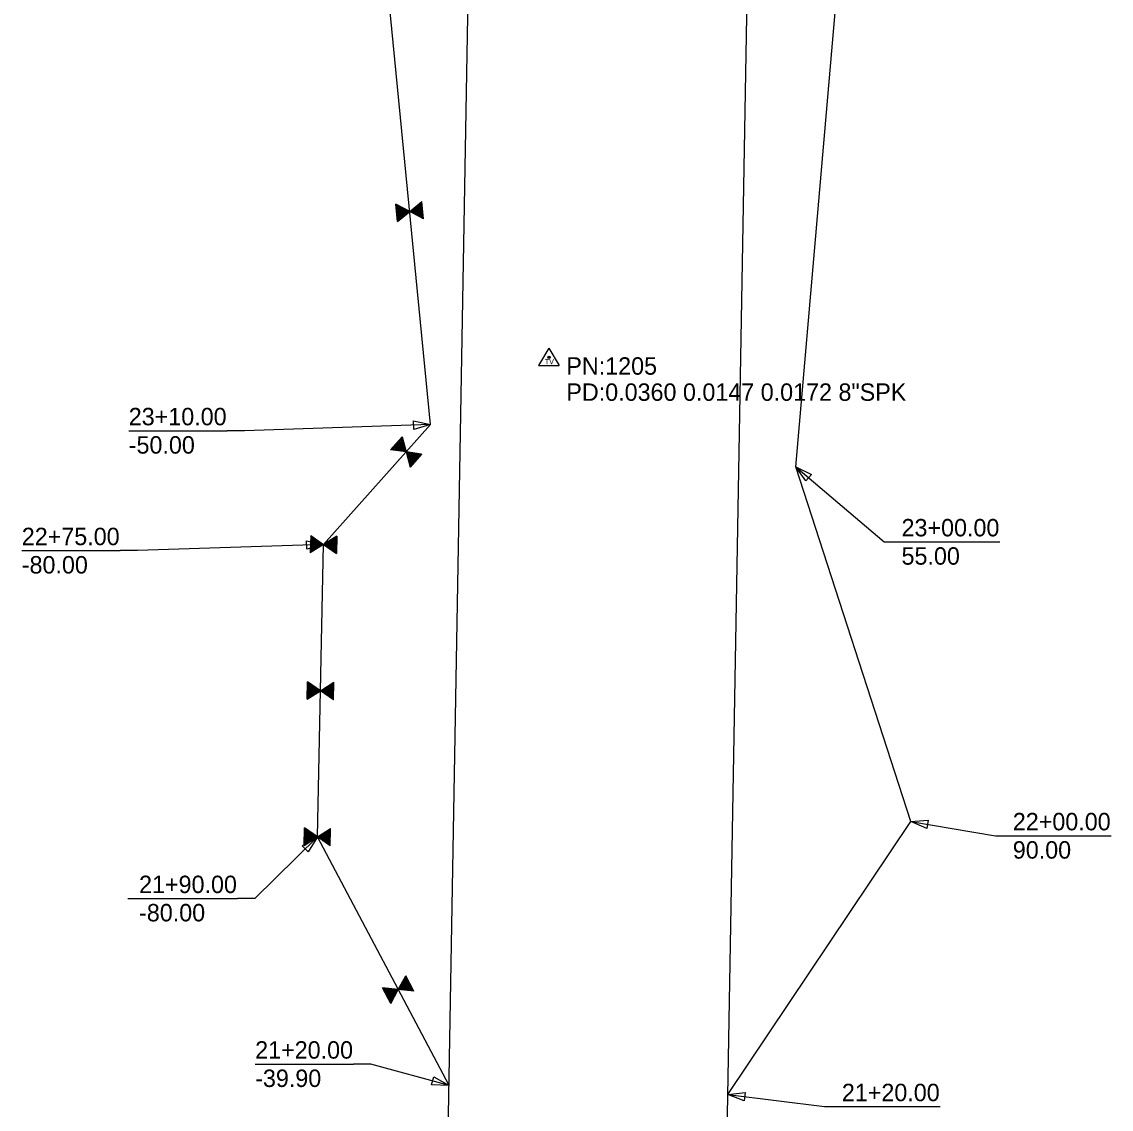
# Model space of a CAD drawing. Extents: x 1443798 to 1476449, y 2041559 to 2057889.
# Drawn here: x 1476064 to 1476376.6, y 2054853 to 2055165 of the extents above; entities that cross this region are included whole.
import ezdxf

# ---------------------------------------------------------------- set-up
doc = ezdxf.new("R2010")
doc.units = 0
for name, color, linetype in [('Plan Notes', 7, 'Continuous'), ('R_Proposed Fence', 7, 'Continuous'), ('R_ROW', 7, 'Continuous'), ('S_EXIST_ROW', 7, 'Continuous'), ('S_SECONDARY_CTL', 7, 'Continuous'), ('S_SECONDARY_CTL_ANNOT', 7, 'Continuous')]:
    doc.layers.add(name, color=color, linetype=linetype)

msp = doc.modelspace()

# ---------------------------------------------------------------- linework, layer by layer
at = {"layer": 'Plan Notes'}
for p, q in [((1476094.73, 2055047.66), (1476122.96, 2055047.66)), ((1476316.45, 2055015.79), (1476344.68, 2055015.79)), ((1476064.04, 2055013.26), (1476092.27, 2055013.26)), ((1476348.37, 2054931.44), (1476376.6, 2054931.44)), ((1476094.46, 2054913.43), (1476125.92, 2054913.43)), ((1476131, 2054865.91), (1476159.23, 2054865.91)), ((1476299.32, 2054853.71), (1476327.56, 2054853.71))]:
    msp.add_line(p, q, dxfattribs=at)
for points in [[(1476181.31, 2055049.43), (1476127.96, 2055047.66), (1476122.96, 2055047.66)], [(1476286.09, 2055037.35), (1476311.45, 2055015.79), (1476316.45, 2055015.79)], [(1476150.62, 2055015.03), (1476097.27, 2055013.26), (1476092.27, 2055013.26)], [(1476319.08, 2054935.51), (1476343.37, 2054931.44), (1476348.37, 2054931.44)], [(1476148.84, 2054931.09), (1476130.92, 2054913.43), (1476125.92, 2054913.43)], [(1476186.62, 2054859.81), (1476164.23, 2054865.91), (1476159.23, 2054865.91)], [(1476266.59, 2054857.19), (1476294.32, 2054853.71), (1476299.32, 2054853.71)]]:
    msp.add_lwpolyline(points, dxfattribs=at)
for points in [[(1476181.31, 2055049.43), (1476176.5, 2055048.06), (1476176.42, 2055050.48)], [(1476286.09, 2055037.35), (1476290.57, 2055035.14), (1476289, 2055033.29)], [(1476150.62, 2055015.03), (1476145.82, 2055013.66), (1476145.74, 2055016.08)], [(1476319.08, 2054935.51), (1476324.06, 2054935.9), (1476323.66, 2054933.51)], [(1476148.84, 2054931.09), (1476146.24, 2054926.82), (1476144.53, 2054928.55)], [(1476186.62, 2054859.81), (1476181.62, 2054859.92), (1476182.26, 2054862.26)], [(1476266.59, 2054857.19), (1476271.55, 2054857.79), (1476271.25, 2054855.38)]]:
    msp.add_lwpolyline(points, close=True, dxfattribs=at)
at = {"layer": 'R_Proposed Fence'}
for p, q in [((1476175.34, 2055110.56), (1476171.37, 2055112.68)), ((1476175.25, 2055110.51), (1476171.38, 2055112.58)), ((1476175, 2055110.36), (1476171.41, 2055112.28)), ((1476174.84, 2055110.17), (1476171.44, 2055111.98)), ((1476174.61, 2055110.01), (1476171.46, 2055111.69)), ((1476175.34, 2055110.56), (1476178.83, 2055113.41)), ((1476175.44, 2055110.53), (1476178.84, 2055113.31)), ((1476175.71, 2055110.43), (1476178.87, 2055113.01)), ((1476175.92, 2055110.27), (1476178.9, 2055112.71)), ((1476176.17, 2055110.16), (1476178.93, 2055112.42)), ((1476176.39, 2055110.02), (1476178.96, 2055112.12)), ((1476176.67, 2055109.92), (1476178.99, 2055111.82)), ((1476174.42, 2055109.83), (1476171.49, 2055111.39)), ((1476174.16, 2055109.68), (1476171.52, 2055111.09)), ((1476174, 2055109.48), (1476171.55, 2055110.79)), ((1476173.75, 2055109.33), (1476171.58, 2055110.49)), ((1476173.55, 2055109.15), (1476171.61, 2055110.19)), ((1476173.16, 2055108.8), (1476171.67, 2055109.59)), ((1476172.97, 2055108.62), (1476171.7, 2055109.29)), ((1476172.74, 2055108.45), (1476171.73, 2055109)), ((1476172.51, 2055108.29), (1476171.76, 2055108.7)), ((1476173.29, 2055109.01), (1476171.79, 2055109.81)), ((1476171.85, 2055107.71), (1476175.34, 2055110.56)), ((1476179.32, 2055108.44), (1476175.34, 2055110.56)), ((1476176.87, 2055109.76), (1476179.02, 2055111.52)), ((1476177.15, 2055109.67), (1476179.05, 2055111.22)), ((1476177.37, 2055109.53), (1476179.08, 2055110.92)), ((1476177.65, 2055109.43), (1476178.98, 2055110.52)), ((1476177.83, 2055109.25), (1476179.13, 2055110.32)), ((1476178.05, 2055109.11), (1476179.16, 2055110.02)), ((1476178.3, 2055109), (1476179.19, 2055109.72)), ((1476178.56, 2055108.88), (1476179.22, 2055109.43)), ((1476178.78, 2055108.74), (1476179.25, 2055109.13)), ((1476179.03, 2055108.63), (1476179.28, 2055108.83)), ((1476179.26, 2055108.49), (1476179.31, 2055108.53)), ((1476172.32, 2055108.11), (1476171.79, 2055108.4)), ((1476172.09, 2055107.95), (1476171.82, 2055108.1)), ((1476171.9, 2055107.77), (1476171.84, 2055107.8)), ((1476173.16, 2055045.93), (1476174.3, 2055041.57)), ((1476174.03, 2055042.45), (1476170.5, 2055042.94)), ((1476173.98, 2055042.7), (1476170.7, 2055043.17)), ((1476173.87, 2055042.97), (1476170.9, 2055043.39)), ((1476173.85, 2055043.23), (1476171.1, 2055043.62)), ((1476173.73, 2055043.5), (1476171.3, 2055043.84)), ((1476173.68, 2055043.76), (1476171.5, 2055044.06)), ((1476173.56, 2055044.03), (1476171.87, 2055044.27)), ((1476173.57, 2055044.28), (1476171.9, 2055044.51)), ((1476173.52, 2055044.54), (1476172.1, 2055044.74)), ((1476173.44, 2055044.8), (1476172.3, 2055044.96)), ((1476173.35, 2055045.07), (1476172.5, 2055045.19)), ((1476173.3, 2055045.33), (1476172.7, 2055045.41)), ((1476173.21, 2055045.59), (1476172.9, 2055045.63)), ((1476173.17, 2055045.85), (1476173.1, 2055045.86)), ((1476174.3, 2055041.57), (1476169.83, 2055042.2)), ((1476174.25, 2055041.66), (1476169.9, 2055042.27)), ((1476174.14, 2055041.93), (1476170.1, 2055042.5)), ((1476174.12, 2055042.18), (1476170.3, 2055042.72)), ((1476174.3, 2055041.57), (1476175.43, 2055037.2)), ((1476178.76, 2055040.94), (1476174.3, 2055041.57)), ((1476174.39, 2055041.53), (1476175.5, 2055037.28)), ((1476174.67, 2055041.45), (1476175.7, 2055037.5)), ((1476174.93, 2055041.46), (1476175.9, 2055037.73)), ((1476175.2, 2055041.4), (1476176.1, 2055037.95)), ((1476175.46, 2055041.38), (1476176.3, 2055038.18)), ((1476175.74, 2055041.3), (1476176.5, 2055038.4)), ((1476176, 2055041.31), (1476176.7, 2055038.62)), ((1476176.28, 2055041.22), (1476176.9, 2055038.85)), ((1476176.54, 2055041.2), (1476177.1, 2055039.07)), ((1476176.83, 2055041.11), (1476177.26, 2055039.46)), ((1476177.07, 2055041.16), (1476177.5, 2055039.52)), ((1476177.34, 2055041.14), (1476177.7, 2055039.74)), ((1476177.61, 2055041.08), (1476177.9, 2055039.97)), ((1476177.88, 2055041.02), (1476178.1, 2055040.19)), ((1476178.15, 2055041.01), (1476178.3, 2055040.42)), ((1476178.42, 2055040.95), (1476178.5, 2055040.64)), ((1476178.68, 2055040.93), (1476178.7, 2055040.87)), ((1476150.53, 2055015.07), (1476146.82, 2055012.71)), ((1476150.62, 2055015.03), (1476146.82, 2055012.61)), ((1476150.27, 2055015.2), (1476146.83, 2055013.01)), ((1476149.85, 2055015.52), (1476146.84, 2055013.61)), ((1476150.09, 2055015.38), (1476146.84, 2055013.31)), ((1476149.65, 2055015.69), (1476146.85, 2055013.91)), ((1476149.2, 2055016), (1476146.86, 2055014.51)), ((1476149.38, 2055015.82), (1476146.86, 2055014.21)), ((1476148.94, 2055016.13), (1476146.87, 2055014.81)), ((1476148.73, 2055016.29), (1476146.88, 2055015.11)), ((1476148.11, 2055016.78), (1476146.89, 2055016.01)), ((1476148.31, 2055016.62), (1476146.89, 2055015.71)), ((1476147.87, 2055016.93), (1476146.9, 2055016.31)), ((1476147.43, 2055017.24), (1476146.91, 2055016.91)), ((1476147.63, 2055017.07), (1476146.91, 2055016.61)), ((1476147.19, 2055017.38), (1476146.92, 2055017.21)), ((1476146.93, 2055017.61), (1476150.62, 2055015.03)), ((1476146.98, 2055017.55), (1476146.93, 2055017.52)), ((1476148.46, 2055016.42), (1476147.02, 2055015.5)), ((1476154.43, 2055017.45), (1476150.62, 2055015.03)), ((1476150.62, 2055015.03), (1476154.32, 2055012.45)), ((1476150.72, 2055015.07), (1476154.32, 2055012.55)), ((1476150.99, 2055015.18), (1476154.33, 2055012.85)), ((1476151.17, 2055015.36), (1476154.34, 2055013.15)), ((1476151.42, 2055015.49), (1476154.34, 2055013.45)), ((1476151.63, 2055015.65), (1476154.35, 2055013.75)), ((1476151.9, 2055015.76), (1476154.35, 2055014.05)), ((1476152.09, 2055015.94), (1476154.36, 2055014.35)), ((1476152.36, 2055016.06), (1476154.37, 2055014.65)), ((1476152.57, 2055016.21), (1476154.37, 2055014.95)), ((1476152.84, 2055016.33), (1476154.24, 2055015.35)), ((1476153, 2055016.52), (1476154.39, 2055015.55)), ((1476153.21, 2055016.68), (1476154.39, 2055015.85)), ((1476153.46, 2055016.81), (1476154.4, 2055016.15)), ((1476153.7, 2055016.94), (1476154.41, 2055016.45)), ((1476153.91, 2055017.1), (1476154.41, 2055016.76)), ((1476154.16, 2055017.24), (1476154.42, 2055017.05)), ((1476154.37, 2055017.39), (1476154.43, 2055017.36)), ((1476148.46, 2054972.32), (1476146, 2054974.04)), ((1476148.73, 2054972.44), (1476146.01, 2054974.34)), ((1476149.18, 2054972.73), (1476146.02, 2054974.94)), ((1476148.94, 2054972.6), (1476146.02, 2054974.64)), ((1476149.64, 2054973.02), (1476146.03, 2054975.54)), ((1476149.37, 2054972.91), (1476146.03, 2054975.24)), ((1476149.73, 2054973.06), (1476146.04, 2054975.64)), ((1476149.73, 2054973.06), (1476153.54, 2054975.48)), ((1476149.82, 2054973.02), (1476153.53, 2054975.38)), ((1476150.09, 2054972.89), (1476153.53, 2054975.08)), ((1476150.27, 2054972.71), (1476153.52, 2054974.78)), ((1476150.51, 2054972.57), (1476153.51, 2054974.48)), ((1476150.71, 2054972.4), (1476153.51, 2054974.18)), ((1476145.93, 2054970.64), (1476149.73, 2054973.06)), ((1476146.2, 2054970.85), (1476145.94, 2054971.03)), ((1476146.65, 2054971.14), (1476145.95, 2054971.63)), ((1476146.44, 2054970.99), (1476145.95, 2054971.33)), ((1476147.14, 2054971.41), (1476145.96, 2054972.24)), ((1476146.9, 2054971.28), (1476145.96, 2054971.93)), ((1476147.36, 2054971.57), (1476145.97, 2054972.54)), ((1476147.79, 2054971.88), (1476145.98, 2054973.14)), ((1476148, 2054972.03), (1476145.99, 2054973.44)), ((1476148.27, 2054972.15), (1476146, 2054973.74)), ((1476147.51, 2054971.76), (1476146.11, 2054972.74)), ((1476153.43, 2054970.48), (1476149.73, 2054973.06)), ((1476150.97, 2054972.27), (1476153.5, 2054973.88)), ((1476151.16, 2054972.09), (1476153.49, 2054973.58)), ((1476151.42, 2054971.96), (1476153.49, 2054973.28)), ((1476151.62, 2054971.79), (1476153.48, 2054972.98)), ((1476151.89, 2054971.67), (1476153.33, 2054972.59)), ((1476152.04, 2054971.47), (1476153.47, 2054972.38)), ((1476152.25, 2054971.3), (1476153.46, 2054972.08)), ((1476152.49, 2054971.16), (1476153.46, 2054971.78)), ((1476152.73, 2054971.02), (1476153.45, 2054971.48)), ((1476152.93, 2054970.85), (1476153.44, 2054971.17)), ((1476145.99, 2054970.7), (1476145.93, 2054970.73)), ((1476153.17, 2054970.71), (1476153.44, 2054970.87)), ((1476153.38, 2054970.54), (1476153.43, 2054970.57)), ((1476148.84, 2054931.09), (1476145.14, 2054933.67)), ((1476148.75, 2054931.05), (1476145.14, 2054933.57)), ((1476148.84, 2054931.09), (1476152.64, 2054933.51)), ((1476148.93, 2054931.05), (1476152.64, 2054933.41)), ((1476145.04, 2054928.67), (1476148.84, 2054931.09)), ((1476146.25, 2054929.44), (1476145.07, 2054930.27)), ((1476146.46, 2054929.6), (1476145.08, 2054930.57)), ((1476146.9, 2054929.91), (1476145.09, 2054931.17)), ((1476147.38, 2054930.18), (1476145.1, 2054931.77)), ((1476147.11, 2054930.06), (1476145.1, 2054931.47)), ((1476147.57, 2054930.36), (1476145.11, 2054932.07)), ((1476148.04, 2054930.63), (1476145.12, 2054932.67)), ((1476147.83, 2054930.47), (1476145.12, 2054932.37)), ((1476148.29, 2054930.76), (1476145.13, 2054932.97)), ((1476148.48, 2054930.94), (1476145.14, 2054933.27)), ((1476146.62, 2054929.79), (1476145.22, 2054930.77)), ((1476152.54, 2054928.51), (1476148.84, 2054931.09)), ((1476149.2, 2054930.92), (1476152.63, 2054933.11)), ((1476149.38, 2054930.74), (1476152.63, 2054932.81)), ((1476149.62, 2054930.6), (1476152.62, 2054932.51)), ((1476149.82, 2054930.43), (1476152.62, 2054932.21)), ((1476150.08, 2054930.3), (1476152.61, 2054931.91)), ((1476150.26, 2054930.12), (1476152.6, 2054931.61)), ((1476150.53, 2054929.99), (1476152.6, 2054931.31)), ((1476150.73, 2054929.83), (1476152.59, 2054931.01)), ((1476151, 2054929.7), (1476152.44, 2054930.62)), ((1476151.15, 2054929.5), (1476152.58, 2054930.41)), ((1476145.09, 2054928.73), (1476145.04, 2054928.76)), ((1476145.55, 2054929.02), (1476145.05, 2054929.36)), ((1476145.31, 2054928.88), (1476145.05, 2054929.06)), ((1476145.76, 2054929.18), (1476145.06, 2054929.67)), ((1476146.01, 2054929.31), (1476145.07, 2054929.97)), ((1476151.36, 2054929.33), (1476152.57, 2054930.11)), ((1476151.6, 2054929.19), (1476152.56, 2054929.81)), ((1476151.84, 2054929.05), (1476152.56, 2054929.51)), ((1476152.04, 2054928.88), (1476152.55, 2054929.21)), ((1476152.28, 2054928.74), (1476152.55, 2054928.91)), ((1476152.48, 2054928.57), (1476152.54, 2054928.6)), ((1476172.05, 2054887.31), (1476174.19, 2054891.27)), ((1476172.15, 2054887.32), (1476174.24, 2054891.18)), ((1476172.44, 2054887.33), (1476174.38, 2054890.92)), ((1476172.69, 2054887.26), (1476174.52, 2054890.65)), ((1476172.97, 2054887.25), (1476174.66, 2054890.39)), ((1476173.23, 2054887.21), (1476174.8, 2054890.12)), ((1476173.52, 2054887.22), (1476174.94, 2054889.86)), ((1476172.05, 2054887.31), (1476167.57, 2054887.76)), ((1476171.99, 2054887.23), (1476167.61, 2054887.67)), ((1476171.81, 2054887), (1476167.75, 2054887.4)), ((1476171.73, 2054886.75), (1476167.89, 2054887.14)), ((1476171.58, 2054886.52), (1476168.03, 2054886.87)), ((1476171.47, 2054886.28), (1476168.18, 2054886.61)), ((1476169.91, 2054883.34), (1476172.05, 2054887.31)), ((1476176.53, 2054886.85), (1476172.05, 2054887.31)), ((1476173.77, 2054887.15), (1476175.08, 2054889.59)), ((1476174.06, 2054887.17), (1476175.22, 2054889.33)), ((1476174.32, 2054887.12), (1476175.36, 2054889.06)), ((1476174.61, 2054887.14), (1476175.43, 2054888.65)), ((1476174.84, 2054887.04), (1476175.65, 2054888.53)), ((1476175.1, 2054887), (1476175.79, 2054888.26)), ((1476175.38, 2054886.99), (1476175.93, 2054888)), ((1476175.66, 2054886.98), (1476176.07, 2054887.73)), ((1476175.92, 2054886.93), (1476176.21, 2054887.47)), ((1476176.2, 2054886.92), (1476176.35, 2054887.2)), ((1476176.46, 2054886.88), (1476176.49, 2054886.94)), ((1476171.29, 2054886.04), (1476168.32, 2054886.34)), ((1476171.21, 2054885.8), (1476168.46, 2054886.08)), ((1476171.04, 2054885.57), (1476168.6, 2054885.81)), ((1476170.93, 2054885.33), (1476168.74, 2054885.55)), ((1476170.7, 2054884.85), (1476169.02, 2054885.02)), ((1476170.74, 2054885.09), (1476169.04, 2054885.26)), ((1476170.59, 2054884.61), (1476169.16, 2054884.75)), ((1476170.44, 2054884.37), (1476169.3, 2054884.48)), ((1476170.29, 2054884.13), (1476169.44, 2054884.22)), ((1476170.19, 2054883.89), (1476169.58, 2054883.95)), ((1476170.04, 2054883.66), (1476169.72, 2054883.69)), ((1476169.93, 2054883.42), (1476169.86, 2054883.42))]:
    msp.add_line(p, q, dxfattribs=at)
for points in [[(1476171.85, 2055107.71), (1476171.37, 2055112.68)], [(1476179.32, 2055108.44), (1476178.83, 2055113.41)], [(1476173.16, 2055045.93), (1476169.83, 2055042.2)], [(1476178.76, 2055040.94), (1476175.43, 2055037.2)], [(1476146.93, 2055017.61), (1476146.82, 2055012.61)], [(1476154.43, 2055017.45), (1476154.32, 2055012.45)], [(1476145.93, 2054970.64), (1476146.04, 2054975.64)], [(1476153.43, 2054970.48), (1476153.54, 2054975.48)], [(1476145.04, 2054928.67), (1476145.14, 2054933.67)], [(1476152.54, 2054928.51), (1476152.64, 2054933.51)], [(1476176.53, 2054886.85), (1476174.19, 2054891.27)], [(1476169.91, 2054883.34), (1476167.57, 2054887.76)]]:
    msp.add_lwpolyline(points, dxfattribs=at)
at = {"layer": 'R_ROW'}
for points in [[(1476186.62, 2054859.81), (1476148.84, 2054931.09), (1476150.62, 2055015.03), (1476181.31, 2055049.43), (1476148.04, 2055390.15), (1476173.45, 2055511.72), (1476163.58, 2055669.9), (1476210, 2056068.52)], [(1476266.59, 2054857.19), (1476319.08, 2054935.51), (1476286.09, 2055037.35), (1476312.02, 2055336.9), (1476343.4, 2055406.29), (1476319.91, 2055508.84), (1476306.57, 2055567.05), (1476338.55, 2055666.44), (1476290.01, 2056067.99)]]:
    msp.add_lwpolyline(points, dxfattribs=at)
at = {"layer": 'S_EXIST_ROW'}
for p, q in [((1476156.76, 2053156.06), (1476196.03, 2055396.48)), ((1476254.56, 2054170.96), (1476275.53, 2055367.16))]:
    msp.add_line(p, q, dxfattribs=at)
at = {"layer": 'S_SECONDARY_CTL'}
for p, q in [((1476215.28, 2055071.36), (1476212.27, 2055066.41)), ((1476215.28, 2055071.36), (1476218.23, 2055066.41)), ((1476212.27, 2055066.41), (1476218.23, 2055066.41))]:
    msp.add_line(p, q, dxfattribs=at)
for radius in [0.311, 0.183, 0.103]:
    msp.add_circle((1476215.28, 2055068.75), radius, dxfattribs=at)

# ---------------------------------------------------------------- texts
at = {"layer": 'Plan Notes'}
for s, p in [('23+10.00', (1476094.73, 2055049.23)), ('-50.00', (1476094.73, 2055041.1)), ('23+00.00', (1476316.45, 2055017.35)), ('22+75.00', (1476064.04, 2055014.83)), ('-80.00', (1476064.04, 2055006.7)), ('55.00', (1476316.45, 2055009.23)), ('22+00.00', (1476348.37, 2054933)), ('90.00', (1476348.37, 2054924.88)), ('21+90.00', (1476097.69, 2054914.99)), ('-80.00', (1476097.69, 2054906.87)), ('21+20.00', (1476131, 2054867.48)), ('-39.90', (1476131, 2054859.35)), ('21+20.00', (1476299.32, 2054855.27))]:
    msp.add_text(s, height=5, dxfattribs=at).set_placement(p)
at = {"layer": 'S_SECONDARY_CTL'}
msp.add_text('TV', height=1.5, dxfattribs=at).set_placement((1476214.08, 2055066.74))
at = {"layer": 'S_SECONDARY_CTL_ANNOT'}
for s, p in [('PN:1205', (1476220.28, 2055063.75)), ('PD:0.0360 0.0147 0.0172 8"SPK', (1476220.28, 2055056.25))]:
    msp.add_text(s, height=5, dxfattribs=at).set_placement(p)

doc.saveas('drawing.dxf')
